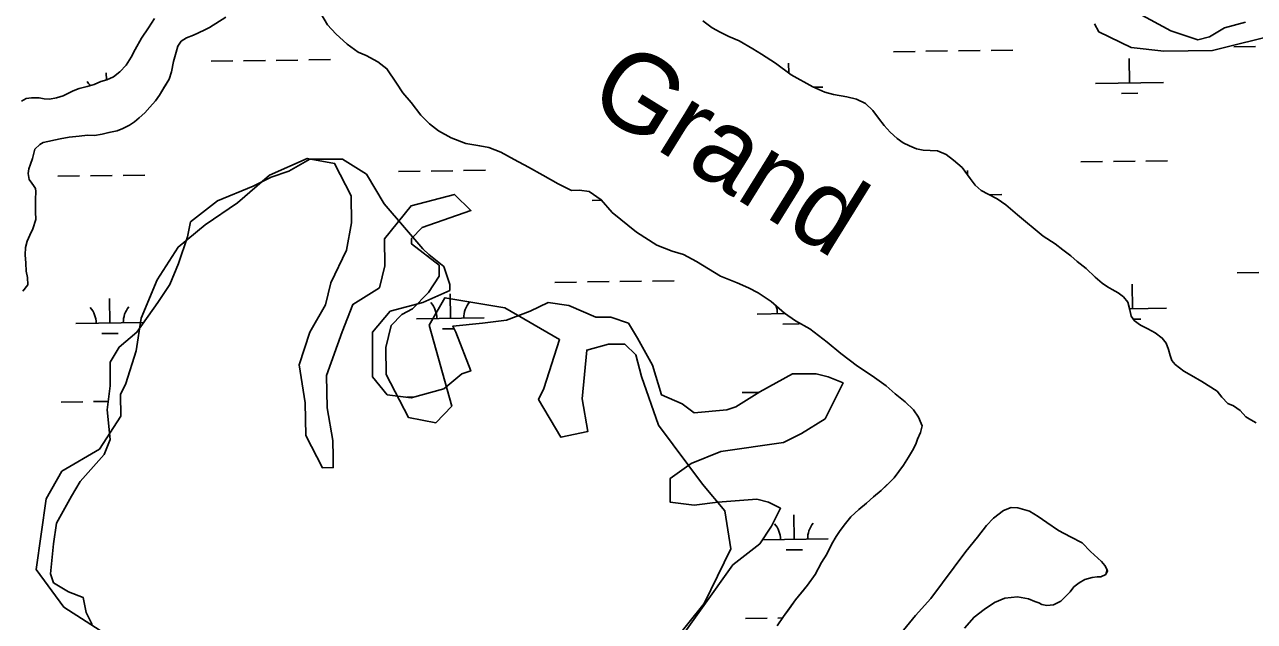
# Model space of a CAD drawing. Extents: x 3767014 to 3805179, y 361544 to 387384.
# Drawn here: x 3773937 to 3775749, y 376266 to 377145 of the extents above; entities that cross this region are included whole.
import ezdxf

# ---------------------------------------------------------------- set-up
doc = ezdxf.new("R2010")
doc.units = 0
for name, color, linetype in [('V-RIVR-IDEN', 7, 'Continuous'), ('V-TOPO-SHOR', 7, 'Continuous'), ('V-WETL-SWMP', 7, 'Continuous')]:
    doc.layers.add(name, color=color, linetype=linetype)

msp = doc.modelspace()

# ---------------------------------------------------------------- linework, layer by layer
at = {"layer": 'V-TOPO-SHOR'}
msp.add_line((3774412.488, 377116.124), (3774428.839, 377104.475), dxfattribs=at)
for points in [[(3774310.385, 377232.17), (3774311.608, 377231.523), (3774331.074, 377215.599), (3774365.743, 377174.799), (3774383.671, 377144.483), (3774396.135, 377131.273), (3774412.488, 377116.124)], [(3773932.732, 377032.056), (3773939.726, 377035.951), (3773947.693, 377037.321), (3773958.58, 377037.141), (3773965.967, 377035.789), (3773973.938, 377035.216), (3773984.432, 377037.172), (3773994.342, 377040.295), (3774008.911, 377047.504), (3774017.849, 377051.014), (3774029.508, 377053.556), (3774039.807, 377056.871), (3774049.521, 377061.16), (3774058.266, 377063.697), (3774068.174, 377068.18), (3774077.884, 377075.58), (3774087.008, 377085.31), (3774094.381, 377097.176), (3774100.199, 377108.456), (3774109.509, 377124.992), (3774119.792, 377140.165), (3774128.717, 377153.783)], [(3773934.626, 376752.145), (3773942.001, 376761.679), (3773941.794, 376772.564), (3773939.451, 376781.698), (3773939.048, 376793.359), (3773938.255, 376805.799), (3773938.436, 376816.491), (3773941.145, 376826.213), (3773945.024, 376834.964), (3773949.677, 376844.301), (3773953.742, 376857.912), (3773953.146, 376869.186), (3773953.513, 376887.459), (3773953.888, 376898.927), (3773953.298, 376903.787), (3773950.572, 376907.867), (3773947.846, 376911.555), (3773943.953, 376916.798), (3773942.386, 376925.74), (3773943.351, 376932.738), (3773946.062, 376939.351), (3773948.968, 376947.907), (3773952.645, 376961.518), (3773959.829, 376968.136), (3773964.879, 376971.253), (3773989.754, 376976.53), (3774002.776, 376979.074), (3774017.74, 376980.841), (3774029.791, 376982.023), (3774040.092, 376981.841), (3774051.753, 376983.799), (3774061.666, 376985.949), (3774073.52, 376988.683), (3774082.068, 376991.804), (3774091.976, 376996.871), (3774099.355, 377001.739), (3774106.347, 377007.773), (3774114.697, 377014.781), (3774122.074, 377023.149), (3774130.032, 377032.49), (3774136.047, 377041.245), (3774143.031, 377052.722), (3774150.404, 377064.781), (3774153.889, 377075.283), (3774156.785, 377090.643), (3774160.463, 377104.448), (3774162.978, 377113.005), (3774167.83, 377120.396), (3774175.987, 377125.461), (3774186.287, 377129.36), (3774201.829, 377136.571), (3774209.986, 377140.858), (3774233.683, 377155.853)], [(3774936.737, 377150.352), (3774950.365, 377140.45), (3774962.235, 377133.851), (3774975.08, 377127.449), (3774990.061, 377120.855), (3775010.496, 377109.407), (3775023.149, 377101.446), (3775043.583, 377088.247), (3775066.943, 377071.16), (3775098.664, 377053.113), (3775116.566, 377045.55), (3775129.212, 377042.064), (3775148.861, 377038.392), (3775162.865, 377035.298), (3775176.099, 377028.701)], [(3775513.817, 377146.191), (3775519.949, 377134.342), (3775568.007, 377111.142), (3775615.817, 377105.839), (3775687.407, 377106.833), (3775788.494, 377132.105), (3775841.938, 377150.749)], [(3774428.839, 377104.475), (3774440.513, 377099.433), (3774457.64, 377090.116), (3774471.266, 377080.022), (3774485.295, 377058.645), (3774494.648, 377044.653), (3774506.723, 377030.276), (3774521.137, 377011.623), (3774533.988, 376998.802), (3774547.224, 376988.706), (3774565.908, 376978.226), (3774587.701, 376970.085), (3774607.931, 376966.221), (3774621.159, 376963.902), (3774639.058, 376957.312), (3774658.521, 376946.054), (3774679.926, 376934.8), (3774700.945, 376923.157), (3774723.52, 376910.349), (3774742.98, 376900.648), (3774755.039, 376901.051), (3774769.043, 376899.124), (3774786.951, 376887.088), (3774802.921, 376868.437), (3774839.13, 376839.308), (3774868.713, 376820.284), (3774891.673, 376811.367), (3774908.405, 376806.329), (3774927.476, 376795.852), (3774944.993, 376785.372), (3774962.898, 376774.501), (3774987.415, 376764.419), (3775003.76, 376757.435), (3775018.162, 376750.064), (3775037.237, 376737.25), (3775057.094, 376720.16), (3775073.443, 376708.511), (3775094.462, 376696.868), (3775119.769, 376677.061), (3775140.016, 376660.749), (3775164.542, 376642.108), (3775186.341, 376627.744), (3775206.586, 376612.988), (3775219.824, 376601.335), (3775235.008, 376589.294), (3775247.056, 376577.641)], [(3775176.099, 377028.701), (3775187.003, 377018.408), (3775195.377, 377007.332), (3775203.756, 376996.257), (3775212.519, 376986.348), (3775223.031, 376977.415), (3775231.985, 376970.814), (3775240.937, 376966.352), (3775251.443, 376962.086), (3775261.366, 376960.152), (3775271.673, 376959.776), (3775282.565, 376959.012), (3775295.018, 376953.58), (3775306.115, 376945.233), (3775318.767, 376934.55), (3775330.652, 376918.23), (3775338.053, 376908.32), (3775346.814, 376900.744), (3775357.128, 376895.116), (3775370.168, 376888.522), (3775383.015, 376879.396), (3775400.146, 376864.636), (3775438.303, 376833.176), (3775455.627, 376821.917), (3775467.112, 376813.18), (3775478.792, 376804.246), (3775488.137, 376796.089), (3775501.567, 376785.603), (3775514.613, 376772.785), (3775524.931, 376764.044), (3775533.107, 376758.609), (3775539.918, 376754.922), (3775548.481, 376749.876), (3775556.268, 376743.857), (3775563.083, 376736.087), (3775566.016, 376725.003), (3775567.777, 376715.281), (3775572.842, 376708.871), (3775581.407, 376702.268), (3775592.304, 376697.029), (3775603.009, 376691.209), (3775613.519, 376683.248), (3775619.168, 376675.863), (3775622.875, 376666.535), (3775625.025, 376657.589), (3775627.755, 376650.399), (3775632.82, 376644.181), (3775645.474, 376634.471), (3775656.566, 376628.262), (3775672.135, 376619.529), (3775694.712, 376604.97), (3775701.338, 376596.032), (3775710.293, 376586.902), (3775718.467, 376583.218), (3775728.199, 376576.421), (3775736.96, 376567.485), (3775743.969, 376563.021), (3775751.948, 376558.558)], [(3774750.139, 376057.638), (3774938.828, 376292.195), (3774977.698, 376372.714), (3774968.925, 376428.576), (3774936.384, 376468.113), (3774871.192, 376555.184), (3774846.204, 376626.817), (3774837.763, 376658.691), (3774821.548, 376674.461), (3774797.56, 376674.128), (3774765.686, 376665.688), (3774758.689, 376593.61), (3774767.352, 376545.744), (3774727.481, 376537.192), (3774694.719, 376592.721), (3774702.493, 376608.825), (3774725.482, 376681.125), (3774725.482, 376681.125), (3774644.853, 376727.992), (3774556.672, 376742.762), (3774533.238, 376702.448), (3774566.89, 376582.948), (3774543.234, 376558.626), (3774503.142, 376566.067), (3774470.268, 376629.593), (3774469.712, 376669.574), (3774477.264, 376701.67), (3774493.035, 376717.885), (3774508.916, 376726.103), (3774532.572, 376750.425), (3774548.231, 376774.636), (3774548.009, 376790.629), (3774507.583, 376822.059), (3774507.472, 376830.055), (3774523.243, 376846.27), (3774594.876, 376871.258), (3774594.876, 376871.258), (3774570.554, 376894.914), (3774506.806, 376878.032), (3774467.491, 376829.499), (3774468.046, 376789.518), (3774460.494, 376757.422), (3774420.846, 376732.878), (3774405.409, 376692.674), (3774382.309, 376628.371), (3774382.975, 376580.393), (3774391.638, 376532.527), (3774391.971, 376508.538), (3774392.193, 376492.545), (3774376.201, 376492.323), (3774351.546, 376539.967), (3774350.879, 376587.945), (3774342.105, 376643.808), (3774357.431, 376692.008), (3774380.865, 376732.322), (3774388.417, 376764.418), (3774411.739, 376812.729), (3774419.18, 376852.822), (3774418.625, 376892.803), (3774393.969, 376940.448), (3774353.877, 376947.888), (3774298.236, 376923.122), (3774250.814, 376882.474), (3774203.281, 376849.823), (3774163.744, 376817.282), (3774132.425, 376768.86), (3774109.214, 376712.553), (3774101.884, 376664.464), (3774086.558, 376616.265), (3774078.784, 376600.161), (3774079.228, 376568.176), (3774047.909, 376519.754), (3773992.38, 376486.991), (3773968.946, 376446.677), (3773954.398, 376342.503), (3773995.157, 376287.085), (3774067.79, 376240.107)], [(3775247.056, 376577.641), (3775254.337, 376566.603), (3775258.519, 376557.559), (3775259.645, 376554.026)], [(3775259.645, 376554.026), (3775258.396, 376548.181), (3775257.173, 376544.288), (3775253.137, 376534.57), (3775250.298, 376526.789), (3775245.494, 376517.862), (3775239.888, 376507.776), (3775232.311, 376496.149), (3775218.78, 376477.566), (3775208.089, 376467.154), (3775199.381, 376458.669), (3775188.316, 376449.434), (3775178.033, 376440.19), (3775166.572, 376430.568), (3775154.708, 376419.779), (3775146.764, 376410.113), (3775139.2, 376399.66), (3775133.226, 376391.138), (3775126.831, 376380.28), (3775119.202, 376364.746), (3775111.618, 376352.73), (3775102.396, 376334.871), (3775090.857, 376319.389), (3775084.9, 376312.04), (3775073.378, 376297.731), (3775063.826, 376284.568), (3775055.466, 376272.952), (3775046.299, 376259.392)], [(3775083.374, 376056.814), (3775121.303, 376117.3), (3775144.306, 376142.411), (3775164.927, 376164.814), (3775182.397, 376185.304), (3775200.303, 376209.304), (3775216.627, 376232.156), (3775232.149, 376253.062), (3775250.024, 376274.72), (3775272.634, 376299.832), (3775323.965, 376368.743), (3775341.445, 376390.016), (3775354.572, 376407.434), (3775364.878, 376418.245), (3775379.877, 376429.387), (3775390.877, 376433.542), (3775401.041, 376433.409)], [(3775401.041, 376433.409), (3775417.786, 376428.5), (3775430.582, 376420.513), (3775443.759, 376411.741), (3775460.802, 376399.789), (3775478.271, 376390.569), (3775495.358, 376381.746), (3775508.09, 376369.069), (3775523.921, 376354.008), (3775528.927, 376348.079), (3775532.361, 376341.777)], [(3775532.361, 376341.777), (3775530.319, 376335.158), (3775522.848, 376331.74), (3775517.761, 376331.414), (3775510.327, 376330.73), (3775499.732, 376327.74), (3775491.065, 376322.774), (3775483.168, 376316.622), (3775477.989, 376309.261), (3775464.13, 376295.763), (3775453.505, 376290.428), (3775443.328, 376289.387), (3775435.923, 376291.048), (3775431.649, 376293.059), (3775425.816, 376295.48), (3775416.481, 376299.121), (3775400.493, 376302.069), (3775381.702, 376299.967), (3775366.377, 376293.913), (3775350.994, 376283.561), (3775336.386, 376272.416), (3775322.095, 376255.794)]]:
    msp.add_lwpolyline(points, dxfattribs=at)
at = {"layer": 'V-WETL-SWMP'}
for p, q in [((3774128.718, 377153.783), (3774119.793, 377140.165)), ((3774109.509, 377124.991), (3774100.199, 377108.457)), ((3774119.793, 377140.165), (3774109.509, 377124.991)), ((3774100.199, 377108.457), (3774094.381, 377097.175)), ((3775265.364, 377105.729), (3775297.357, 377106.174)), ((3775313.353, 377106.396), (3775345.346, 377106.84)), ((3775361.342, 377107.062), (3775393.335, 377107.507)), ((3775719.168, 377112.033), (3775751.16, 377112.477)), ((3774094.381, 377097.175), (3774087.008, 377085.309)), ((3774212.052, 377090.94), (3774244.049, 377091.384)), ((3774260.048, 377091.606), (3774292.045, 377092.051)), ((3774308.043, 377092.273), (3774340.04, 377092.717)), ((3774356.039, 377092.94), (3774388.035, 377093.384)), ((3775063.224, 377074.044), (3775063.026, 377088.175)), ((3775217.375, 377105.062), (3775249.368, 377105.507)), ((3775565.322, 377059.15), (3775564.818, 377095.146)), ((3774057.826, 377063.57), (3774057.68, 377074.052)), ((3774077.884, 377075.579), (3774068.174, 377068.18)), ((3774087.008, 377085.309), (3774077.884, 377075.579)), ((3774029.509, 377053.555), (3774017.849, 377051.014)), ((3774039.808, 377056.872), (3774029.509, 377053.555)), ((3774049.522, 377061.16), (3774039.808, 377056.872)), ((3774058.266, 377063.698), (3774049.522, 377061.16)), ((3774068.174, 377068.18), (3774058.266, 377063.698)), ((3775099.946, 377052.686), (3775113.518, 377052.874)), ((3775515.333, 377058.456), (3775615.31, 377059.845)), ((3773939.725, 377035.951), (3773932.732, 377032.055)), ((3773947.693, 377037.322), (3773939.725, 377035.951)), ((3773958.579, 377037.141), (3773947.693, 377037.322)), ((3773965.967, 377035.789), (3773958.579, 377037.141)), ((3773973.938, 377035.215), (3773965.967, 377035.789)), ((3773984.432, 377037.172), (3773973.938, 377035.215)), ((3773994.342, 377040.294), (3773984.432, 377037.172)), ((3774008.912, 377047.504), (3773994.342, 377040.294)), ((3774017.849, 377051.014), (3774008.912, 377047.504)), ((3775553.541, 377043.555), (3775577.535, 377043.888)), ((3775493.548, 376942.713), (3775525.54, 376943.157)), ((3775541.537, 376943.38), (3775573.529, 376943.824)), ((3775589.525, 376944.046), (3775621.518, 376944.491)), ((3774488.242, 376928.586), (3774520.239, 376929.031)), ((3774536.238, 376929.253), (3774568.234, 376929.697)), ((3774584.233, 376929.92), (3774616.23, 376930.364)), ((3775326.755, 376923.737), (3775326.668, 376929.964)), ((3773986.383, 376921.615), (3774018.379, 376922.059)), ((3774034.378, 376922.281), (3774066.375, 376922.726)), ((3774082.373, 376922.948), (3774114.37, 376923.393)), ((3775358.686, 376894.406), (3775377.161, 376894.663)), ((3774773.704, 376886.117), (3774787.616, 376886.31)), ((3775723.827, 376779.399), (3775755.82, 376779.843)), ((3774718.533, 376765.268), (3774750.53, 376765.713)), ((3774766.528, 376765.935), (3774798.525, 376766.379)), ((3774814.524, 376766.602), (3774846.52, 376767.046)), ((3774862.519, 376767.268), (3774894.516, 376767.713)), ((3775569.981, 376726.516), (3775569.477, 376762.512)), ((3774564.661, 376712.384), (3774564.16, 376748.38)), ((3774062.801, 376705.412), (3774062.301, 376741.409)), ((3775565.682, 376726.457), (3775619.97, 376727.211)), ((3774514.665, 376711.689), (3774614.656, 376713.078)), ((3775016.525, 376718.661), (3775058.382, 376719.242)), ((3775571.142, 376711.1), (3775582.195, 376711.254)), ((3774012.806, 376704.718), (3774112.795, 376706.107)), ((3774051.016, 376689.816), (3774075.014, 376690.149)), ((3774552.876, 376696.788), (3774570.066, 376697.026)), ((3775054.736, 376703.759), (3775078.733, 376704.092)), ((3774994.723, 376602.915), (3775019.179, 376603.254)), ((3773991.003, 376588.972), (3774023, 376589.416)), ((3774038.999, 376589.639), (3774060.486, 376589.937)), ((3774500.45, 376596.049), (3774510.162, 376596.184)), ((3775071.141, 376386.712), (3775070.641, 376422.709)), ((3775024.481, 376386.064), (3775121.136, 376387.407)), ((3775059.356, 376371.116), (3775083.354, 376371.449)), ((3774999.343, 376270.272), (3775031.34, 376270.716)), ((3775047.339, 376270.938), (3775054.169, 376271.033))]:
    msp.add_line(p, q, dxfattribs=at)
for points in [[(3774365.742, 377174.8), (3774383.671, 377144.483), (3774396.134, 377131.273), (3774412.489, 377116.123), (3774428.839, 377104.474), (3774440.514, 377099.432), (3774457.64, 377090.117), (3774471.266, 377080.021), (3774485.295, 377058.645), (3774494.647, 377044.653), (3774506.722, 377030.276), (3774521.136, 377011.623), (3774533.988, 376998.803), (3774547.225, 376988.706), (3774565.908, 376978.227), (3774587.7, 376970.085), (3774607.93, 376966.22), (3774621.158, 376963.902), (3774639.058, 376957.311), (3774658.52, 376946.055), (3774679.927, 376934.801), (3774700.945, 376923.157), (3774723.521, 376910.349), (3774742.981, 376900.648), (3774755.038, 376901.052), (3774769.043, 376899.124), (3774786.95, 376887.088), (3774802.92, 376868.437), (3774839.129, 376839.308), (3774868.713, 376820.285), (3774891.673, 376811.367), (3774908.405, 376806.33), (3774927.477, 376795.851), (3774944.993, 376785.371), (3774962.898, 376774.501), (3774987.415, 376764.418), (3775003.76, 376757.436), (3775018.161, 376750.064), (3775037.236, 376737.251), (3775057.094, 376720.16), (3775073.444, 376708.511), (3775094.462, 376696.868), (3775119.769, 376677.061), (3775140.015, 376660.749), (3775164.542, 376642.109), (3775186.342, 376627.744), (3775206.586, 376612.987), (3775219.825, 376601.335), (3775235.009, 376589.295), (3775247.057, 376577.641), (3775254.338, 376566.602), (3775258.519, 376557.558), (3775259.645, 376554.026), (3775258.396, 376548.18), (3775257.173, 376544.287), (3775253.137, 376534.569), (3775250.299, 376526.79), (3775245.493, 376517.863), (3775239.889, 376507.775), (3775232.311, 376496.149), (3775218.779, 376477.566), (3775199.38, 376458.669), (3775188.316, 376449.434), (3775178.033, 376440.189), (3775166.573, 376430.568), (3775154.707, 376419.78), (3775146.763, 376410.113), (3775139.2, 376399.659), (3775133.226, 376391.139), (3775126.831, 376380.28), (3775119.201, 376364.746), (3775111.618, 376352.729), (3775102.395, 376334.872), (3775090.858, 376319.389), (3775073.378, 376297.731), (3775055.466, 376272.952), (3775046.299, 376259.393)], [(3775578.016, 377161.954), (3775626.31, 377135.596), (3775665.823, 377122.417), (3775683.385, 377126.81), (3775705.336, 377139.989), (3775736.069, 377148.775)], [(3774156.786, 377090.642), (3774160.463, 377104.448), (3774162.979, 377113.004), (3774167.83, 377120.396), (3774175.988, 377125.46), (3774186.286, 377129.36), (3774201.828, 377136.571), (3774209.987, 377140.858), (3774233.683, 377155.854)], [(3775539.918, 376754.923), (3775533.107, 376758.609), (3775524.932, 376764.045), (3775514.614, 376772.784), (3775501.568, 376785.604), (3775488.136, 376796.09), (3775478.791, 376804.247), (3775467.111, 376813.179), (3775455.626, 376821.917), (3775438.303, 376833.176), (3775400.147, 376864.636), (3775383.014, 376879.396), (3775370.168, 376888.521), (3775357.129, 376895.117), (3775346.815, 376900.745), (3775338.054, 376908.319), (3775330.652, 376918.229), (3775318.768, 376934.551), (3775306.114, 376945.232), (3775295.019, 376953.581), (3775282.565, 376959.012), (3775271.673, 376959.776), (3775261.365, 376960.153), (3775251.444, 376962.086), (3775240.937, 376966.352), (3775231.985, 376970.814), (3775223.031, 376977.415), (3775212.518, 376986.349), (3775203.755, 376996.257), (3775195.378, 377007.332), (3775187.002, 377018.407), (3775176.099, 377028.702), (3775162.866, 377035.298), (3775148.86, 377038.393), (3775129.212, 377042.064), (3775116.567, 377045.55), (3775098.665, 377053.113), (3775066.943, 377071.161), (3775043.584, 377088.247), (3775023.148, 377101.447), (3775010.497, 377109.406), (3774990.062, 377120.855), (3774975.079, 377127.45), (3774962.235, 377133.852), (3774950.364, 377140.45), (3774936.738, 377150.352)], [(3773934.627, 376752.145), (3773942.002, 376761.679), (3773941.794, 376772.564), (3773939.451, 376781.697), (3773939.048, 376793.36), (3773938.255, 376805.799), (3773938.436, 376816.491), (3773941.146, 376826.213), (3773945.023, 376834.965), (3773949.677, 376844.301), (3773953.743, 376857.913), (3773953.146, 376869.186), (3773953.512, 376887.459), (3773953.887, 376898.928), (3773953.298, 376903.787), (3773950.572, 376907.866), (3773943.952, 376916.799), (3773942.386, 376925.739), (3773943.35, 376932.738), (3773946.063, 376939.35), (3773948.968, 376947.907), (3773952.645, 376961.518), (3773959.829, 376968.136), (3773964.88, 376971.252), (3773989.754, 376976.531), (3774002.775, 376979.074), (3774017.74, 376980.841), (3774029.791, 376982.022), (3774040.093, 376981.84), (3774051.754, 376983.798), (3774061.665, 376985.948), (3774073.519, 376988.684), (3774082.068, 376991.805), (3774091.976, 376996.871), (3774099.356, 377001.739), (3774106.347, 377007.773), (3774114.697, 377014.781), (3774122.073, 377023.149), (3774130.032, 377032.489), (3774136.047, 377041.244), (3774150.403, 377064.781), (3774153.889, 377075.282), (3774156.786, 377090.642)], [(3774827.267, 376705.082), (3774800.924, 376713.868), (3774778.973, 376713.868), (3774739.459, 376731.44), (3774708.727, 376735.833), (3774682.385, 376722.654), (3774647.262, 376709.475), (3774612.139, 376705.082), (3774568.236, 376700.689), (3774572.626, 376691.903), (3774594.578, 376634.795), (3774581.407, 376630.402), (3774555.065, 376608.437), (3774506.771, 376595.258), (3774471.648, 376599.651), (3774449.696, 376626.009), (3774449.696, 376691.903), (3774476.038, 376722.654), (3774524.332, 376735.833), (3774563.845, 376753.405), (3774563.845, 376762.191), (3774555.065, 376788.549), (3774533.113, 376806.121), (3774524.332, 376814.907), (3774467.258, 376880.802), (3774440.916, 376924.732), (3774405.793, 376946.696), (3774357.499, 376946.696), (3774326.767, 376929.125), (3774300.425, 376920.339), (3774274.083, 376907.16), (3774221.398, 376885.195), (3774181.885, 376854.444), (3774177.495, 376832.479), (3774164.324, 376792.942), (3774151.153, 376762.191), (3774133.591, 376735.833), (3774102.859, 376691.903), (3774076.517, 376669.939), (3774063.346, 376647.974), (3774063.346, 376612.83), (3774058.955, 376577.686), (3774063.346, 376533.756), (3774054.565, 376511.791), (3774019.442, 376472.254), (3774006.271, 376450.289), (3773984.32, 376410.753), (3773979.929, 376380.002), (3773975.539, 376336.072), (3773979.929, 376322.893), (3774001.881, 376309.714), (3774023.833, 376300.928), (3774028.223, 376278.963), (3774037.004, 376261.391)], [(3775751.947, 376558.558), (3775743.968, 376563.021), (3775736.961, 376567.486), (3775728.199, 376576.421), (3775718.467, 376583.217), (3775710.294, 376586.902), (3775701.337, 376596.032), (3775694.713, 376604.97), (3775672.136, 376619.529), (3775656.567, 376628.261), (3775645.474, 376634.471), (3775632.82, 376644.18), (3775627.756, 376650.398), (3775625.025, 376657.59), (3775622.875, 376666.534), (3775619.168, 376675.864), (3775613.519, 376683.248), (3775603.008, 376691.209), (3775592.304, 376697.03), (3775581.407, 376702.268), (3775572.841, 376708.87), (3775567.777, 376715.282), (3775566.015, 376725.004), (3775563.084, 376736.086), (3775556.268, 376743.857), (3775548.481, 376749.876), (3775539.918, 376754.923)], [(3774893.122, 376226.247), (3774980.929, 376349.251), (3775020.442, 376380.002), (3775038.003, 376406.36), (3775051.174, 376432.717), (3775033.613, 376441.503), (3775016.052, 376445.896), (3774958.977, 376441.503), (3774923.854, 376437.11), (3774888.731, 376441.503), (3774888.731, 376476.647), (3774919.464, 376498.612), (3774963.367, 376516.184), (3775055.565, 376529.363), (3775081.907, 376542.542), (3775117.03, 376564.507), (3775143.372, 376617.223), (3775121.42, 376626.009), (3775103.859, 376630.402), (3775068.736, 376630.402), (3775020.442, 376604.044), (3774985.319, 376582.079), (3774972.148, 376577.686), (3774923.854, 376573.293), (3774906.293, 376586.472), (3774875.56, 376599.651), (3774862.389, 376643.581), (3774840.438, 376683.117), (3774827.267, 376705.082)], [(3775083.375, 376056.815), (3775121.304, 376117.301), (3775164.927, 376164.813), (3775182.396, 376185.303), (3775200.302, 376209.305), (3775216.628, 376232.156), (3775232.148, 376253.062), (3775250.023, 376274.719), (3775272.634, 376299.833), (3775323.965, 376368.744), (3775341.444, 376390.016), (3775354.572, 376407.435), (3775364.878, 376418.246), (3775379.878, 376429.386), (3775390.878, 376433.542), (3775401.041, 376433.409)], [(3775401.041, 376433.409), (3775417.786, 376428.499), (3775430.581, 376420.513), (3775443.758, 376411.74), (3775460.802, 376399.789), (3775478.272, 376390.569), (3775495.357, 376381.745), (3775508.091, 376369.069), (3775523.922, 376354.007), (3775528.926, 376348.078), (3775532.362, 376341.778), (3775532.737, 376340.6), (3775530.32, 376335.159), (3775522.848, 376331.739), (3775517.762, 376331.415), (3775510.326, 376330.73), (3775499.732, 376327.741), (3775491.066, 376322.773), (3775483.168, 376316.622), (3775477.989, 376309.262), (3775464.13, 376295.762), (3775453.506, 376290.428), (3775443.328, 376289.388), (3775435.923, 376291.049), (3775431.649, 376293.06), (3775425.817, 376295.481), (3775416.482, 376299.122), (3775400.493, 376302.068), (3775381.702, 376299.968), (3775366.377, 376293.914), (3775350.995, 376283.561), (3775336.386, 376272.416), (3775322.095, 376255.793)]]:
    msp.add_lwpolyline(points, dxfattribs=at)
for centre, start, end in [((3774002.936, 377037.763), 29.117813, 41.567696), ((3774007.557, 376705.12), 0.024037, 41.567696), ((3774118.032, 376706.654), 140.024034, 181.567693), ((3774509.416, 376712.091), 0.024037, 41.567696), ((3774619.892, 376713.626), 140.024034, 181.567693), ((3775011.276, 376719.063), 0.024037, 19.926007), ((3775015.897, 376386.42), 0.024037, 41.567696), ((3775126.372, 376387.954), 140.024034, 181.567693)]:
    msp.add_arc(centre, 35.246, start, end, dxfattribs=at)

# ---------------------------------------------------------------- texts
at = {"layer": 'V-RIVR-IDEN'}
msp.add_text('Grand', height=116, rotation=328.172515, dxfattribs=at).set_placement((3774762.602, 377026.597))

doc.saveas('drawing.dxf')
